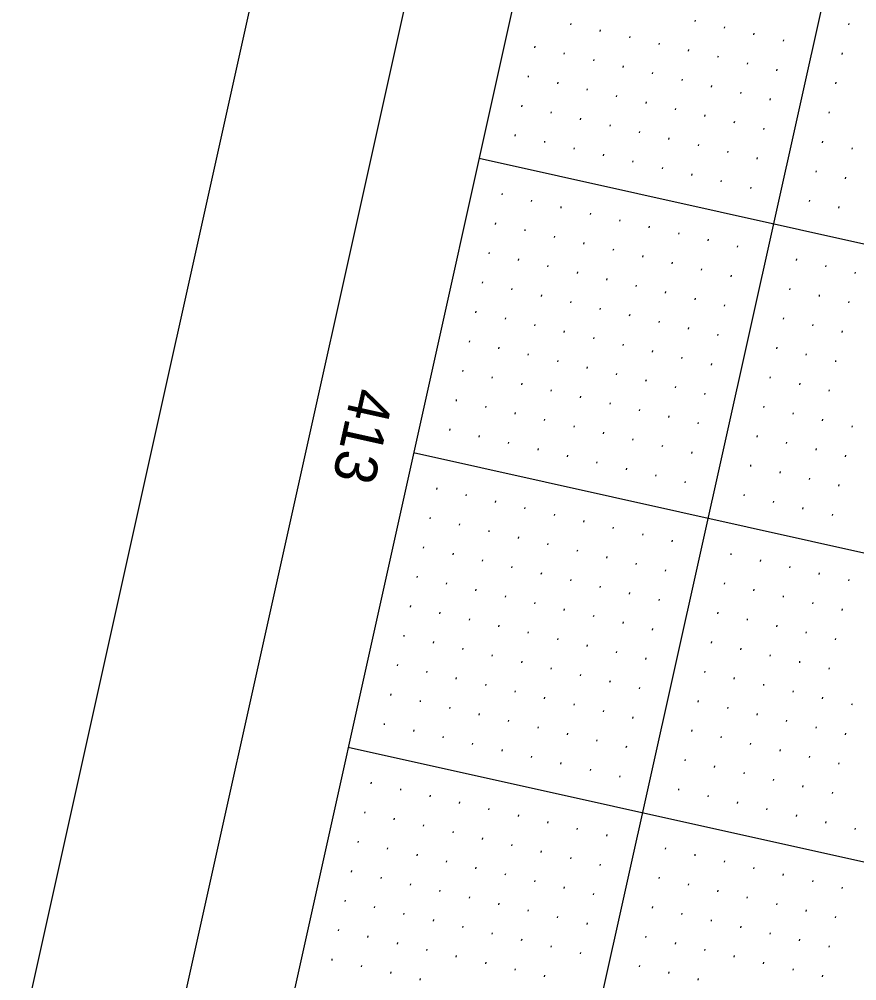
# Model space of a CAD drawing. Extents: x 2149268 to 2150830, y 142155 to 144285.
# Drawn here: x 2149580.1 to 2149719, y 143558.2 to 143717.6 of the extents above; entities that cross this region are included whole.
import ezdxf

# ---------------------------------------------------------------- set-up
doc = ezdxf.new("R2010")
doc.units = 0
for name, color, linetype in [('SHT_Plan_Profile_Sheet_Sta_Txt', 7, 'Continuous'), ('SHT_Plot_Shape_Half', 7, 'Continuous'), ('SHT_Profile_Grid_Major', 7, 'Continuous'), ('SHT_Profile_Grid_Minor', 7, 'Continuous'), ('SHT_Sheet_Border', 7, 'Continuous')]:
    doc.layers.add(name, color=color, linetype=linetype)

msp = doc.modelspace()

# ---------------------------------------------------------------- linework, layer by layer
at = {"layer": 'SHT_Plot_Shape_Half'}
msp.add_lwpolyline([(2150772.24, 143840.86), (2150403.25, 142181.39), (2149329.47, 142420.15), (2149698.47, 144079.62)], close=True, dxfattribs=at)
at = {"layer": 'SHT_Profile_Grid_Major'}
for p, q in [((2149767.6, 143964.37), (2149425.74, 142426.92)), ((2149656.39, 143694.58), (2150100.54, 143595.82)), ((2149645.53, 143645.77), (2150089.69, 143547.01)), ((2149634.68, 143596.96), (2150078.83, 143498.2))]:
    msp.add_line(p, q, dxfattribs=at)
at = {"layer": 'SHT_Profile_Grid_Minor'}
for p, q in [((2149692.21, 143717.47), (2149692.16, 143717.23)), ((2149671.6, 143716.93), (2149671.55, 143716.69)), ((2149676.48, 143715.85), (2149676.43, 143715.6)), ((2149697.09, 143716.39), (2149697.04, 143716.14)), ((2149717.7, 143716.93), (2149717.65, 143716.68)), ((2149681.36, 143714.76), (2149681.31, 143714.52)), ((2149701.97, 143715.3), (2149701.92, 143715.06)), ((2149706.85, 143714.22), (2149706.8, 143713.97)), ((2149665.64, 143713.14), (2149665.58, 143712.89)), ((2149686.24, 143713.68), (2149686.19, 143713.43)), ((2149691.12, 143712.59), (2149691.07, 143712.35)), ((2149670.52, 143712.05), (2149670.46, 143711.81)), ((2149675.4, 143710.97), (2149675.34, 143710.72)), ((2149696.01, 143711.51), (2149695.95, 143711.26)), ((2149716.61, 143712.05), (2149716.56, 143711.8)), ((2149680.28, 143709.88), (2149680.22, 143709.64)), ((2149700.89, 143710.42), (2149700.83, 143710.18)), ((2149705.77, 143709.34), (2149705.71, 143709.09)), ((2149664.55, 143708.26), (2149664.5, 143708.01)), ((2149685.16, 143708.8), (2149685.1, 143708.55)), ((2149669.43, 143707.17), (2149669.38, 143706.93)), ((2149690.04, 143707.71), (2149689.99, 143707.47)), ((2149694.92, 143706.63), (2149694.87, 143706.38)), ((2149715.53, 143707.17), (2149715.47, 143706.92)), ((2149674.31, 143706.09), (2149674.26, 143705.84)), ((2149679.19, 143705), (2149679.14, 143704.76)), ((2149699.8, 143705.54), (2149699.75, 143705.3)), ((2149663.47, 143703.38), (2149663.41, 143703.13)), ((2149684.07, 143703.92), (2149684.02, 143703.67)), ((2149704.68, 143704.46), (2149704.63, 143704.21)), ((2149668.35, 143702.29), (2149668.29, 143702.05)), ((2149688.95, 143702.83), (2149688.9, 143702.59)), ((2149693.84, 143701.75), (2149693.78, 143701.5)), ((2149714.44, 143702.28), (2149714.39, 143702.04)), ((2149673.23, 143701.21), (2149673.17, 143700.96)), ((2149678.11, 143700.12), (2149678.05, 143699.88)), ((2149698.72, 143700.66), (2149698.66, 143700.42)), ((2149662.38, 143698.5), (2149662.33, 143698.25)), ((2149682.99, 143699.04), (2149682.93, 143698.79)), ((2149703.6, 143699.57), (2149703.54, 143699.33)), ((2149667.26, 143697.41), (2149667.21, 143697.17)), ((2149687.87, 143697.95), (2149687.81, 143697.71)), ((2149692.75, 143696.86), (2149692.7, 143696.62)), ((2149713.36, 143697.4), (2149713.3, 143697.16)), ((2149672.14, 143696.32), (2149672.09, 143696.08)), ((2149677.02, 143695.24), (2149676.97, 143695)), ((2149697.63, 143695.78), (2149697.58, 143695.54)), ((2149718.24, 143696.32), (2149718.18, 143696.07)), ((2149681.9, 143694.15), (2149681.85, 143693.91)), ((2149702.51, 143694.69), (2149702.46, 143694.45)), ((2149686.78, 143693.07), (2149686.73, 143692.82)), ((2149691.66, 143691.98), (2149691.61, 143691.74)), ((2149712.27, 143692.52), (2149712.22, 143692.28)), ((2149696.55, 143690.9), (2149696.49, 143690.65)), ((2149717.15, 143691.44), (2149717.1, 143691.19)), ((2149660.21, 143688.73), (2149660.15, 143688.49)), ((2149701.43, 143689.81), (2149701.37, 143689.57)), ((2149665.09, 143687.65), (2149665.04, 143687.4)), ((2149711.19, 143687.64), (2149711.13, 143687.4)), ((2149669.97, 143686.56), (2149669.92, 143686.32)), ((2149674.85, 143685.48), (2149674.8, 143685.23)), ((2149716.07, 143686.56), (2149716.01, 143686.31)), ((2149659.12, 143683.85), (2149659.07, 143683.61)), ((2149679.73, 143684.39), (2149679.68, 143684.15)), ((2149664, 143682.77), (2149663.95, 143682.52)), ((2149684.61, 143683.31), (2149684.56, 143683.06)), ((2149668.89, 143681.68), (2149668.83, 143681.44)), ((2149689.49, 143682.22), (2149689.44, 143681.98)), ((2149694.37, 143681.14), (2149694.32, 143680.89)), ((2149673.77, 143680.6), (2149673.71, 143680.35)), ((2149678.65, 143679.51), (2149678.59, 143679.27)), ((2149699.26, 143680.05), (2149699.2, 143679.81)), ((2149658.04, 143678.97), (2149657.98, 143678.73)), ((2149662.92, 143677.89), (2149662.87, 143677.64)), ((2149683.53, 143678.43), (2149683.47, 143678.18)), ((2149709.02, 143677.88), (2149708.96, 143677.64)), ((2149667.8, 143676.8), (2149667.75, 143676.56)), ((2149688.41, 143677.34), (2149688.35, 143677.1)), ((2149693.29, 143676.26), (2149693.24, 143676.01)), ((2149713.9, 143676.8), (2149713.84, 143676.55)), ((2149672.68, 143675.72), (2149672.63, 143675.47)), ((2149677.56, 143674.63), (2149677.51, 143674.39)), ((2149698.17, 143675.17), (2149698.12, 143674.93)), ((2149718.78, 143675.71), (2149718.72, 143675.47)), ((2149656.95, 143674.09), (2149656.9, 143673.85)), ((2149661.83, 143673.01), (2149661.78, 143672.76)), ((2149682.44, 143673.55), (2149682.39, 143673.3)), ((2149707.93, 143673), (2149707.88, 143672.76)), ((2149666.71, 143671.92), (2149666.66, 143671.68)), ((2149687.32, 143672.46), (2149687.27, 143672.22)), ((2149692.2, 143671.38), (2149692.15, 143671.13)), ((2149712.81, 143671.91), (2149712.76, 143671.67)), ((2149671.6, 143670.84), (2149671.54, 143670.59)), ((2149676.48, 143669.75), (2149676.42, 143669.51)), ((2149697.08, 143670.29), (2149697.03, 143670.05)), ((2149717.69, 143670.83), (2149717.64, 143670.59)), ((2149655.87, 143669.21), (2149655.81, 143668.97)), ((2149660.75, 143668.13), (2149660.69, 143667.88)), ((2149681.36, 143668.66), (2149681.3, 143668.42)), ((2149706.85, 143668.12), (2149706.79, 143667.88)), ((2149665.63, 143667.04), (2149665.58, 143666.8)), ((2149686.24, 143667.58), (2149686.18, 143667.34)), ((2149691.12, 143666.49), (2149691.06, 143666.25)), ((2149711.73, 143667.03), (2149711.67, 143666.79)), ((2149670.51, 143665.95), (2149670.46, 143665.71)), ((2149675.39, 143664.87), (2149675.34, 143664.63)), ((2149696, 143665.41), (2149695.95, 143665.17)), ((2149716.61, 143665.95), (2149716.55, 143665.7)), ((2149654.78, 143664.33), (2149654.73, 143664.09)), ((2149659.66, 143663.24), (2149659.61, 143663)), ((2149680.27, 143663.78), (2149680.22, 143663.54)), ((2149705.76, 143663.24), (2149705.71, 143662.99)), ((2149664.54, 143662.16), (2149664.49, 143661.92)), ((2149685.15, 143662.7), (2149685.1, 143662.45)), ((2149690.03, 143661.61), (2149689.98, 143661.37)), ((2149710.64, 143662.15), (2149710.59, 143661.91)), ((2149669.43, 143661.07), (2149669.37, 143660.83)), ((2149674.31, 143659.99), (2149674.25, 143659.74)), ((2149694.91, 143660.53), (2149694.86, 143660.28)), ((2149715.52, 143661.07), (2149715.47, 143660.82)), ((2149653.7, 143659.45), (2149653.64, 143659.2)), ((2149658.58, 143658.36), (2149658.52, 143658.12)), ((2149679.19, 143658.9), (2149679.13, 143658.66)), ((2149704.68, 143658.36), (2149704.62, 143658.11)), ((2149663.46, 143657.28), (2149663.4, 143657.03)), ((2149684.07, 143657.82), (2149684.01, 143657.57)), ((2149688.95, 143656.73), (2149688.89, 143656.49)), ((2149709.56, 143657.27), (2149709.5, 143657.03)), ((2149668.34, 143656.19), (2149668.29, 143655.95)), ((2149693.83, 143655.65), (2149693.77, 143655.4)), ((2149714.44, 143656.19), (2149714.38, 143655.94)), ((2149652.61, 143654.57), (2149652.56, 143654.32)), ((2149673.22, 143655.11), (2149673.17, 143654.86)), ((2149678.1, 143654.02), (2149678.05, 143653.78)), ((2149657.49, 143653.48), (2149657.44, 143653.24)), ((2149662.37, 143652.4), (2149662.32, 143652.15)), ((2149682.98, 143652.94), (2149682.93, 143652.69)), ((2149703.59, 143653.48), (2149703.54, 143653.23)), ((2149708.47, 143652.39), (2149708.42, 143652.15)), ((2149667.25, 143651.31), (2149667.2, 143651.07)), ((2149687.86, 143651.85), (2149687.81, 143651.61)), ((2149692.74, 143650.77), (2149692.69, 143650.52)), ((2149713.35, 143651.31), (2149713.3, 143651.06)), ((2149651.53, 143649.69), (2149651.47, 143649.44)), ((2149672.14, 143650.23), (2149672.08, 143649.98)), ((2149677.02, 143649.14), (2149676.96, 143648.9)), ((2149718.23, 143650.22), (2149718.18, 143649.98)), ((2149656.41, 143648.6), (2149656.35, 143648.36)), ((2149661.29, 143647.52), (2149661.23, 143647.27)), ((2149681.9, 143648.06), (2149681.84, 143647.81)), ((2149702.51, 143648.6), (2149702.45, 143648.35)), ((2149707.39, 143647.51), (2149707.33, 143647.27)), ((2149666.17, 143646.43), (2149666.12, 143646.19)), ((2149686.78, 143646.97), (2149686.72, 143646.73)), ((2149691.66, 143645.89), (2149691.6, 143645.64)), ((2149712.27, 143646.43), (2149712.21, 143646.18)), ((2149671.05, 143645.35), (2149671, 143645.1)), ((2149675.93, 143644.26), (2149675.88, 143644.02)), ((2149717.15, 143645.34), (2149717.09, 143645.1)), ((2149680.81, 143643.18), (2149680.76, 143642.93)), ((2149701.42, 143643.72), (2149701.37, 143643.47)), ((2149706.3, 143642.63), (2149706.25, 143642.39)), ((2149685.69, 143642.09), (2149685.64, 143641.85)), ((2149690.57, 143641.01), (2149690.52, 143640.76)), ((2149711.18, 143641.54), (2149711.13, 143641.3)), ((2149649.36, 143639.93), (2149649.3, 143639.68)), ((2149716.06, 143640.46), (2149716.01, 143640.22)), ((2149654.24, 143638.84), (2149654.18, 143638.6)), ((2149659.12, 143637.76), (2149659.06, 143637.51)), ((2149700.33, 143638.83), (2149700.28, 143638.59)), ((2149705.22, 143637.75), (2149705.16, 143637.51)), ((2149664, 143636.67), (2149663.94, 143636.43)), ((2149710.1, 143636.66), (2149710.04, 143636.42)), ((2149648.27, 143635.04), (2149648.22, 143634.8)), ((2149668.88, 143635.58), (2149668.83, 143635.34)), ((2149673.76, 143634.5), (2149673.71, 143634.26)), ((2149714.98, 143635.58), (2149714.92, 143635.33)), ((2149653.15, 143633.96), (2149653.1, 143633.72)), ((2149658.03, 143632.87), (2149657.98, 143632.63)), ((2149678.64, 143633.41), (2149678.59, 143633.17)), ((2149662.91, 143631.79), (2149662.86, 143631.55)), ((2149683.52, 143632.33), (2149683.47, 143632.08)), ((2149688.4, 143631.24), (2149688.35, 143631)), ((2149647.19, 143630.16), (2149647.13, 143629.92)), ((2149667.79, 143630.7), (2149667.74, 143630.46)), ((2149672.68, 143629.62), (2149672.62, 143629.37)), ((2149652.07, 143629.08), (2149652.01, 143628.83)), ((2149677.56, 143628.53), (2149677.5, 143628.29)), ((2149698.16, 143629.07), (2149698.11, 143628.83)), ((2149656.95, 143627.99), (2149656.89, 143627.75)), ((2149661.83, 143626.91), (2149661.77, 143626.66)), ((2149682.44, 143627.45), (2149682.38, 143627.2)), ((2149703.05, 143627.99), (2149702.99, 143627.74)), ((2149707.93, 143626.9), (2149707.87, 143626.66)), ((2149646.1, 143625.28), (2149646.05, 143625.04)), ((2149666.71, 143625.82), (2149666.65, 143625.58)), ((2149687.32, 143626.36), (2149687.26, 143626.12)), ((2149712.81, 143625.82), (2149712.75, 143625.57)), ((2149650.98, 143624.2), (2149650.93, 143623.95)), ((2149671.59, 143624.74), (2149671.54, 143624.49)), ((2149676.47, 143623.65), (2149676.42, 143623.41)), ((2149697.08, 143624.19), (2149697.02, 143623.95)), ((2149717.69, 143624.73), (2149717.63, 143624.49)), ((2149655.86, 143623.11), (2149655.81, 143622.87)), ((2149660.74, 143622.03), (2149660.69, 143621.78)), ((2149681.35, 143622.57), (2149681.3, 143622.32)), ((2149701.96, 143623.11), (2149701.91, 143622.86)), ((2149706.84, 143622.02), (2149706.79, 143621.78)), ((2149645.02, 143620.4), (2149644.96, 143620.16)), ((2149665.62, 143620.94), (2149665.57, 143620.7)), ((2149686.23, 143621.48), (2149686.18, 143621.24)), ((2149711.72, 143620.94), (2149711.67, 143620.69)), ((2149649.9, 143619.32), (2149649.84, 143619.07)), ((2149670.5, 143619.86), (2149670.45, 143619.61)), ((2149675.39, 143618.77), (2149675.33, 143618.53)), ((2149695.99, 143619.31), (2149695.94, 143619.07)), ((2149716.6, 143619.85), (2149716.55, 143619.61)), ((2149654.78, 143618.23), (2149654.72, 143617.99)), ((2149659.66, 143617.15), (2149659.6, 143616.9)), ((2149680.27, 143617.69), (2149680.21, 143617.44)), ((2149700.87, 143618.23), (2149700.82, 143617.98)), ((2149705.76, 143617.14), (2149705.7, 143616.9)), ((2149643.93, 143615.52), (2149643.88, 143615.28)), ((2149664.54, 143616.06), (2149664.48, 143615.82)), ((2149685.15, 143616.6), (2149685.09, 143616.36)), ((2149710.64, 143616.06), (2149710.58, 143615.81)), ((2149648.81, 143614.44), (2149648.76, 143614.19)), ((2149669.42, 143614.98), (2149669.37, 143614.73)), ((2149674.3, 143613.89), (2149674.25, 143613.65)), ((2149694.91, 143614.43), (2149694.85, 143614.19)), ((2149715.52, 143614.97), (2149715.46, 143614.73)), ((2149653.69, 143613.35), (2149653.64, 143613.11)), ((2149658.57, 143612.27), (2149658.52, 143612.02)), ((2149679.18, 143612.81), (2149679.13, 143612.56)), ((2149699.79, 143613.35), (2149699.74, 143613.1)), ((2149704.67, 143612.26), (2149704.62, 143612.02)), ((2149642.84, 143610.64), (2149642.79, 143610.4)), ((2149663.45, 143611.18), (2149663.4, 143610.94)), ((2149684.06, 143611.72), (2149684.01, 143611.48)), ((2149709.55, 143611.17), (2149709.5, 143610.93)), ((2149647.73, 143609.56), (2149647.67, 143609.31)), ((2149668.33, 143610.1), (2149668.28, 143609.85)), ((2149673.21, 143609.01), (2149673.16, 143608.77)), ((2149693.82, 143609.55), (2149693.77, 143609.31)), ((2149714.43, 143610.09), (2149714.38, 143609.85)), ((2149652.61, 143608.47), (2149652.55, 143608.23)), ((2149657.49, 143607.39), (2149657.43, 143607.14)), ((2149678.1, 143607.92), (2149678.04, 143607.68)), ((2149698.7, 143608.46), (2149698.65, 143608.22)), ((2149703.58, 143607.38), (2149703.53, 143607.14)), ((2149641.76, 143605.76), (2149641.71, 143605.52)), ((2149662.37, 143606.3), (2149662.31, 143606.06)), ((2149682.98, 143606.84), (2149682.92, 143606.6)), ((2149708.47, 143606.29), (2149708.41, 143606.05)), ((2149646.64, 143604.67), (2149646.59, 143604.43)), ((2149667.25, 143605.21), (2149667.19, 143604.97)), ((2149672.13, 143604.13), (2149672.08, 143603.89)), ((2149692.74, 143604.67), (2149692.68, 143604.42)), ((2149713.35, 143605.21), (2149713.29, 143604.96)), ((2149718.23, 143604.12), (2149718.17, 143603.88)), ((2149651.52, 143603.59), (2149651.47, 143603.35)), ((2149677.01, 143603.04), (2149676.96, 143602.8)), ((2149697.62, 143603.58), (2149697.56, 143603.34)), ((2149656.4, 143602.5), (2149656.35, 143602.26)), ((2149661.28, 143601.42), (2149661.23, 143601.18)), ((2149681.89, 143601.96), (2149681.84, 143601.71)), ((2149702.5, 143602.5), (2149702.45, 143602.25)), ((2149707.38, 143601.41), (2149707.33, 143601.17)), ((2149640.67, 143600.88), (2149640.62, 143600.64)), ((2149645.56, 143599.79), (2149645.5, 143599.55)), ((2149666.16, 143600.33), (2149666.11, 143600.09)), ((2149691.65, 143599.79), (2149691.6, 143599.54)), ((2149712.26, 143600.33), (2149712.21, 143600.08)), ((2149650.44, 143598.71), (2149650.38, 143598.46)), ((2149671.04, 143599.25), (2149670.99, 143599)), ((2149675.93, 143598.16), (2149675.87, 143597.92)), ((2149696.53, 143598.7), (2149696.48, 143598.46)), ((2149717.14, 143599.24), (2149717.09, 143599)), ((2149655.32, 143597.62), (2149655.26, 143597.38)), ((2149660.2, 143596.54), (2149660.14, 143596.29)), ((2149680.81, 143597.08), (2149680.75, 143596.83)), ((2149701.41, 143597.62), (2149701.36, 143597.37)), ((2149706.3, 143596.53), (2149706.24, 143596.29)), ((2149665.08, 143595.45), (2149665.02, 143595.21)), ((2149690.57, 143594.91), (2149690.51, 143594.66)), ((2149711.18, 143595.45), (2149711.12, 143595.2)), ((2149669.96, 143594.37), (2149669.9, 143594.12)), ((2149674.84, 143593.28), (2149674.79, 143593.04)), ((2149695.45, 143593.82), (2149695.39, 143593.58)), ((2149716.06, 143594.36), (2149716, 143594.12)), ((2149679.72, 143592.2), (2149679.67, 143591.95)), ((2149700.33, 143592.74), (2149700.27, 143592.49)), ((2149705.21, 143591.65), (2149705.16, 143591.41)), ((2149638.5, 143591.12), (2149638.45, 143590.87)), ((2149643.38, 143590.03), (2149643.33, 143589.79)), ((2149689.48, 143590.03), (2149689.43, 143589.78)), ((2149710.09, 143590.57), (2149710.04, 143590.32)), ((2149648.27, 143588.95), (2149648.21, 143588.7)), ((2149694.36, 143588.94), (2149694.31, 143588.7)), ((2149714.97, 143589.48), (2149714.92, 143589.24)), ((2149653.15, 143587.86), (2149653.09, 143587.62)), ((2149658.03, 143586.78), (2149657.97, 143586.53)), ((2149699.24, 143587.86), (2149699.19, 143587.61)), ((2149704.12, 143586.77), (2149704.07, 143586.53)), ((2149637.42, 143586.24), (2149637.36, 143585.99)), ((2149642.3, 143585.15), (2149642.24, 143584.91)), ((2149662.91, 143585.69), (2149662.85, 143585.45)), ((2149709.01, 143585.69), (2149708.95, 143585.44)), ((2149647.18, 143584.07), (2149647.13, 143583.82)), ((2149667.79, 143584.61), (2149667.73, 143584.36)), ((2149672.67, 143583.52), (2149672.61, 143583.28)), ((2149713.89, 143584.6), (2149713.83, 143584.36)), ((2149718.77, 143583.51), (2149718.71, 143583.27)), ((2149652.06, 143582.98), (2149652.01, 143582.74)), ((2149656.94, 143581.9), (2149656.89, 143581.65)), ((2149677.55, 143582.44), (2149677.5, 143582.19)), ((2149636.33, 143581.36), (2149636.28, 143581.11)), ((2149641.21, 143580.27), (2149641.16, 143580.03)), ((2149661.82, 143580.81), (2149661.77, 143580.57)), ((2149687.31, 143580.26), (2149687.26, 143580.02)), ((2149646.09, 143579.19), (2149646.04, 143578.94)), ((2149666.7, 143579.73), (2149666.65, 143579.48)), ((2149671.58, 143578.64), (2149671.53, 143578.4)), ((2149692.19, 143579.18), (2149692.14, 143578.94)), ((2149650.98, 143578.1), (2149650.92, 143577.86)), ((2149655.86, 143577.02), (2149655.8, 143576.77)), ((2149676.46, 143577.55), (2149676.41, 143577.31)), ((2149697.07, 143578.09), (2149697.02, 143577.85)), ((2149701.95, 143577.01), (2149701.9, 143576.77)), ((2149635.25, 143576.48), (2149635.19, 143576.23)), ((2149660.74, 143575.93), (2149660.68, 143575.69)), ((2149706.83, 143575.92), (2149706.78, 143575.68)), ((2149640.13, 143575.39), (2149640.07, 143575.15)), ((2149645.01, 143574.3), (2149644.96, 143574.06)), ((2149665.62, 143574.84), (2149665.56, 143574.6)), ((2149686.23, 143575.38), (2149686.17, 143575.14)), ((2149691.11, 143574.3), (2149691.05, 143574.05)), ((2149711.72, 143574.84), (2149711.66, 143574.59)), ((2149649.89, 143573.22), (2149649.84, 143572.98)), ((2149670.5, 143573.76), (2149670.44, 143573.52)), ((2149675.38, 143572.67), (2149675.33, 143572.43)), ((2149695.99, 143573.21), (2149695.93, 143572.97)), ((2149716.6, 143573.75), (2149716.54, 143573.51)), ((2149634.16, 143571.59), (2149634.11, 143571.35)), ((2149654.77, 143572.13), (2149654.72, 143571.89)), ((2149659.65, 143571.05), (2149659.6, 143570.8)), ((2149700.87, 143572.13), (2149700.81, 143571.88)), ((2149705.75, 143571.04), (2149705.7, 143570.8)), ((2149639.04, 143570.51), (2149638.99, 143570.27)), ((2149643.92, 143569.42), (2149643.87, 143569.18)), ((2149664.53, 143569.96), (2149664.48, 143569.72)), ((2149685.14, 143570.5), (2149685.09, 143570.26)), ((2149690.02, 143569.42), (2149689.97, 143569.17)), ((2149710.63, 143569.96), (2149710.58, 143569.71)), ((2149648.8, 143568.34), (2149648.75, 143568.09)), ((2149669.41, 143568.88), (2149669.36, 143568.63)), ((2149674.29, 143567.79), (2149674.24, 143567.55)), ((2149694.9, 143568.33), (2149694.85, 143568.09)), ((2149715.51, 143568.87), (2149715.46, 143568.63)), ((2149633.08, 143566.71), (2149633.02, 143566.47)), ((2149653.69, 143567.25), (2149653.63, 143567.01)), ((2149658.57, 143566.17), (2149658.51, 143565.92)), ((2149699.78, 143567.25), (2149699.73, 143567)), ((2149704.66, 143566.16), (2149704.61, 143565.92)), ((2149637.96, 143565.63), (2149637.9, 143565.38)), ((2149642.84, 143564.54), (2149642.78, 143564.3)), ((2149663.45, 143565.08), (2149663.39, 143564.84)), ((2149684.06, 143565.62), (2149684, 143565.38)), ((2149688.94, 143564.54), (2149688.88, 143564.29)), ((2149709.55, 143565.08), (2149709.49, 143564.83)), ((2149647.72, 143563.46), (2149647.67, 143563.21)), ((2149668.33, 143564), (2149668.27, 143563.75)), ((2149673.21, 143562.91), (2149673.15, 143562.67)), ((2149693.82, 143563.45), (2149693.76, 143563.21)), ((2149714.43, 143563.99), (2149714.37, 143563.75)), ((2149631.99, 143561.83), (2149631.94, 143561.59)), ((2149652.6, 143562.37), (2149652.55, 143562.13)), ((2149657.48, 143561.29), (2149657.43, 143561.04)), ((2149698.7, 143562.37), (2149698.64, 143562.12)), ((2149703.58, 143561.28), (2149703.52, 143561.04)), ((2149636.87, 143560.75), (2149636.82, 143560.5)), ((2149641.75, 143559.66), (2149641.7, 143559.42)), ((2149662.36, 143560.2), (2149662.31, 143559.96)), ((2149682.97, 143560.74), (2149682.92, 143560.5)), ((2149687.85, 143559.66), (2149687.8, 143559.41)), ((2149708.46, 143560.2), (2149708.41, 143559.95)), ((2149646.63, 143558.58), (2149646.58, 143558.33)), ((2149667.24, 143559.12), (2149667.19, 143558.87)), ((2149692.73, 143558.57), (2149692.68, 143558.33)), ((2149713.34, 143559.11), (2149713.29, 143558.87))]:
    msp.add_line(p, q, dxfattribs=at)
at = {"layer": 'SHT_Sheet_Border'}
msp.add_line((2149718.79, 143975.22), (2149433.9, 142694.01), dxfattribs=at)
msp.add_lwpolyline([(2150726.67, 143751.11), (2150384.81, 142213.66), (2149359.84, 142441.57), (2149701.71, 143979.02)], close=True, dxfattribs=at)

# ---------------------------------------------------------------- texts
at = {"layer": 'SHT_Plan_Profile_Sheet_Sta_Txt'}
msp.add_text('413', height=7, rotation=257.4638, dxfattribs=at).set_placement((2149635.44, 143656.8))

doc.saveas('drawing.dxf')
